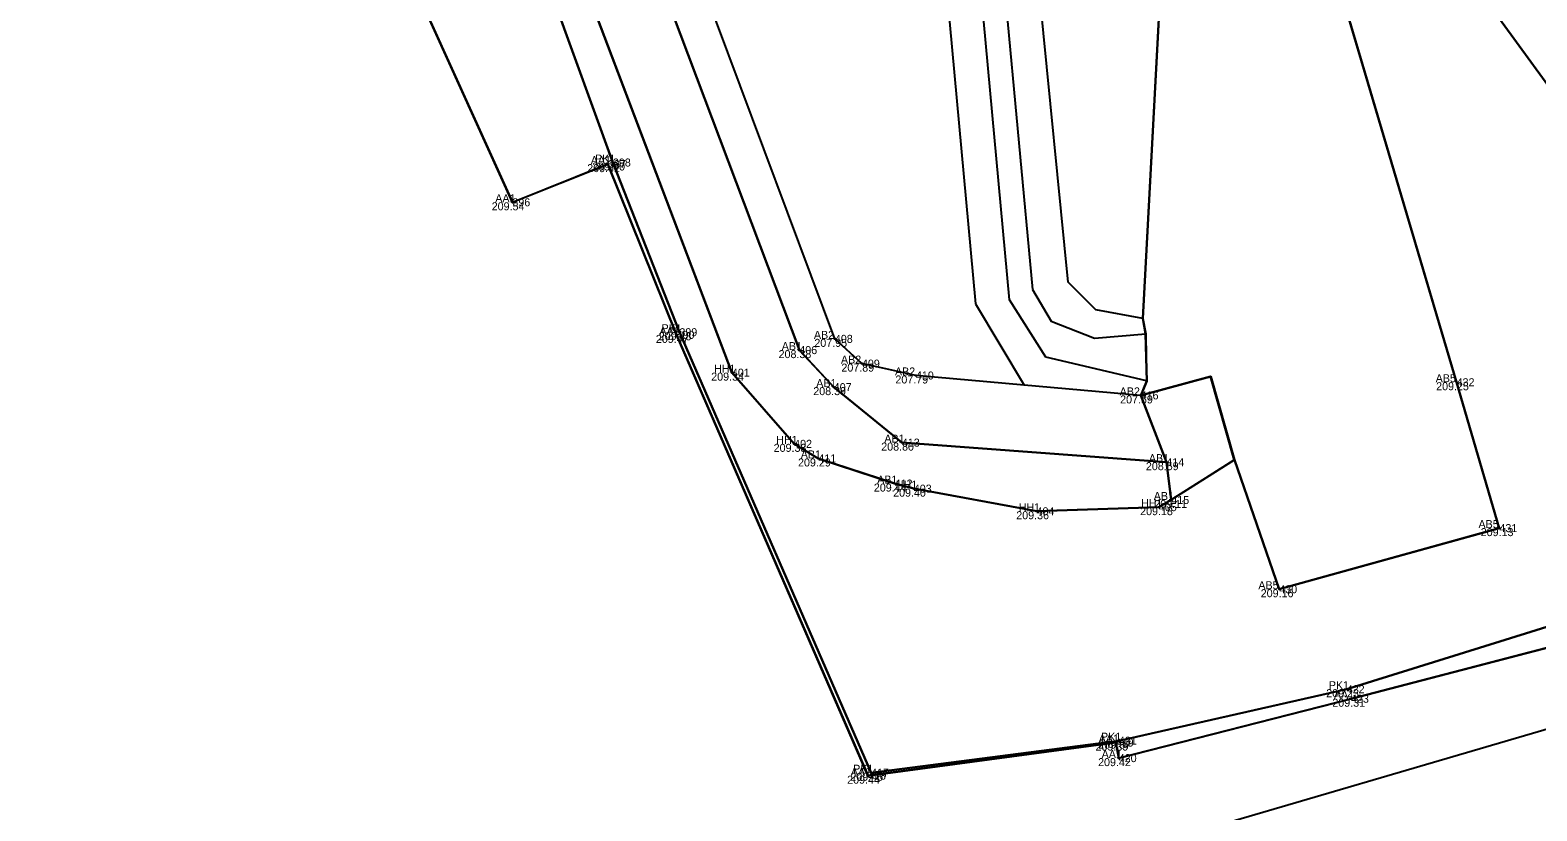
# Model space of a CAD drawing. Extents: x -263091 to -262565, y -1238731 to -1237092.
# Drawn here: x -262849.37 to -262811.71, y -1238702.72 to -1238683.21 of the extents above; entities that cross this region are included whole.
import ezdxf

# ---------------------------------------------------------------- set-up
doc = ezdxf.new("R2010")
doc.units = 0
for name, color, linetype in [('01_Hrana_betónu', 7, 'Continuous'), ('02_Oplotenie', 7, 'Continuous'), ('03_Asfalt', 7, 'Continuous'), ('05_Hrana_terénu', 7, 'Continuous'), ('07_Iné', 7, 'Continuous'), ('08_Mimo_zelene', 7, 'Continuous'), ('10', 7, 'Continuous'), ('Groma (21)', 7, 'Continuous'), ('Groma (22)', 7, 'Continuous'), ('Groma (23)', 7, 'Continuous'), ('Groma (24)', 7, 'Continuous'), ('U001_Betónové_panely_oblast', 7, 'Continuous'), ('U001_Betóny_prídavné', 7, 'Continuous'), ('U001_Ostatné_plochy', 7, 'Continuous'), ('U001_Zeleň_mimo', 7, 'Continuous'), ('U001_Zeleň_vnútro', 7, 'Continuous'), ('U001_Zeleň_zatrávňovač', 7, 'Continuous')]:
    doc.layers.add(name, color=color, linetype=linetype)

msp = doc.modelspace()

# ---------------------------------------------------------------- linework, layer by layer
at = {"layer": '01_Hrana_betónu'}
for points in [[(-262945.09, -1238415.05), (-262943.108, -1238420.999), (-262942.065, -1238424.139), (-262934.754, -1238438.855), (-262923.683, -1238461.06), (-262913.753, -1238481.232), (-262903.896, -1238501.06), (-262894.759, -1238519.856), (-262890.317, -1238530.551), (-262883.158, -1238545.169), (-262873.572, -1238564.111), (-262869.728, -1238571.951), (-262860.562, -1238590.864), (-262854.835, -1238604.812), (-262840.38, -1238642.586), (-262833.174, -1238661.935), (-262826.575, -1238681.018), (-262825.738, -1238690.053), (-262824.527, -1238692.082)], [(-262821.464, -1238691.979), (-262823.978, -1238691.385), (-262824.893, -1238689.953), (-262825.729, -1238680.825), (-262832.468, -1238661.625), (-262839.672, -1238642.452), (-262854.271, -1238604.655), (-262859.863, -1238590.55), (-262868.949, -1238571.69), (-262872.864, -1238563.867), (-262882.403, -1238544.934), (-262889.591, -1238530.296), (-262894.035, -1238519.557), (-262903.102, -1238500.748), (-262912.912, -1238480.97), (-262922.987, -1238460.594), (-262933.962, -1238438.502), (-262941.314, -1238423.977), (-262942.296, -1238420.781), (-262943.962, -1238415.15)], [(-262941.142, -1238415.313), (-262941.461, -1238420.191), (-262940.383, -1238424.238), (-262933.343, -1238438.564), (-262922.27, -1238460.876), (-262912.449, -1238480.877), (-262902.557, -1238500.683), (-262893.416, -1238519.552), (-262889.058, -1238529.686), (-262881.962, -1238544.577), (-262872.106, -1238564.019), (-262868.478, -1238571.232), (-262859.211, -1238590.61), (-262852.998, -1238605.343), (-262846.933, -1238621.173), (-262838.559, -1238643.348), (-262831.894, -1238661.158), (-262825.164, -1238680.62), (-262824.312, -1238689.696), (-262823.847, -1238690.483), (-262822.763, -1238690.91), (-262821.486, -1238690.803)], [(-262821.555, -1238690.42), (-262822.731, -1238690.203), (-262823.426, -1238689.509), (-262824.318, -1238680.43), (-262831.163, -1238660.976), (-262837.946, -1238643.111), (-262846.365, -1238620.94), (-262852.333, -1238605.156), (-262858.618, -1238590.245), (-262867.784, -1238570.905), (-262871.416, -1238563.68), (-262881.223, -1238544.283), (-262888.392, -1238529.442), (-262892.626, -1238519.239), (-262901.725, -1238500.385), (-262911.6, -1238480.51), (-262921.479, -1238460.51), (-262932.607, -1238438.043), (-262939.752, -1238424.147), (-262940.771, -1238420.267), (-262940.559, -1238417.612), (-262940.205, -1238415.315)], [(-262821.612, -1238692.34), (-262824.527, -1238692.082), (-262827.229, -1238691.842), (-262828.578, -1238691.545), (-262829.254, -1238690.927), (-262834.577, -1238676.68), (-262835.677, -1238673.797), (-262838.498, -1238665.964), (-262846.729, -1238644.188), (-262854.634, -1238622.918), (-262863.262, -1238600.529), (-262868.088, -1238589.608)], [(-262868.934, -1238589.993), (-262864.101, -1238600.869), (-262855.602, -1238623.066), (-262847.622, -1238644.482), (-262839.332, -1238666.304), (-262836.604, -1238674.133), (-262835.486, -1238677.015), (-262830.144, -1238691.208), (-262829.282, -1238692.133), (-262827.58, -1238693.519), (-262820.969, -1238694.008)], [(-262820.949, -1238674.974), (-262820.828, -1238676.721), (-262819.978, -1238676.713), (-262819.376, -1238678.614), (-262820.948, -1238679.013), (-262821.555, -1238690.42)]]:
    msp.add_lwpolyline(points, dxfattribs=at)
at = {"layer": '02_Oplotenie'}
msp.add_lwpolyline([(-262896.033, -1238537.323), (-262884.611, -1238562.768), (-262875.332, -1238581.932), (-262871.26, -1238591.133), (-262867.507, -1238600.089), (-262859.113, -1238621.74), (-262850.323, -1238645.054), (-262841.974, -1238667.148), (-262839.469, -1238673.878), (-262839.26, -1238674.43), (-262837.725, -1238678.482), (-262834.801, -1238686.521), (-262833.14, -1238690.761), (-262828.35, -1238701.769), (-262822.156, -1238700.967), (-262816.462, -1238699.68), (-262807.77, -1238696.972), (-262807.339, -1238690.207)], dxfattribs=at)
at = {"layer": '03_Asfalt'}
msp.add_lwpolyline([(-262881.2, -1238585.494), (-262874.644, -1238603.324), (-262866.886, -1238624.256), (-262857.388, -1238650.091), (-262854.721, -1238649.057), (-262851.25, -1238656.85), (-262845.959, -1238668.452), (-262837.314, -1238687.515), (-262834.926, -1238686.561), (-262833.211, -1238690.828), (-262828.426, -1238701.842), (-262822.233, -1238701.015), (-262822.159, -1238701.403), (-262816.354, -1238699.919), (-262807.207, -1238697.538)], dxfattribs=at)
at = {"layer": '05_Hrana_terénu'}
msp.add_lwpolyline([(-262820.846, -1238694.953), (-262821.157, -1238695.132), (-262824.214, -1238695.234), (-262827.282, -1238694.67), (-262827.759, -1238694.543), (-262829.668, -1238693.915), (-262830.272, -1238693.55), (-262831.828, -1238691.771), (-262836.912, -1238678.373), (-262837.725, -1238678.482), (-262838.648, -1238678.516), (-262839.921, -1238675.334), (-262839.26, -1238674.43), (-262838.626, -1238673.561), (-262840.949, -1238666.783), (-262849.249, -1238645.167), (-262857.406, -1238624.309), (-262870.41, -1238590.811)], dxfattribs=at)
at = {"layer": '07_Iné'}
msp.add_lwpolyline([(-262821.612, -1238692.34), (-262820.969, -1238694.008), (-262820.846, -1238694.953), (-262819.273, -1238693.95), (-262819.863, -1238691.866), (-262821.612, -1238692.34)], dxfattribs=at)
at = {"layer": '08_Mimo_zelene'}
msp.add_lwpolyline([(-262817.803, -1238678.214), (-262819.181, -1238678.564), (-262819.376, -1238678.614), (-262820.948, -1238679.013), (-262821.555, -1238690.42), (-262821.486, -1238690.803), (-262821.464, -1238691.979), (-262821.612, -1238692.34), (-262819.863, -1238691.866), (-262819.273, -1238693.95), (-262818.147, -1238697.183), (-262812.645, -1238695.656), (-262813.715, -1238692.011)], close=True, dxfattribs=at)
at = {"layer": '10'}
msp.add_line((-262857.845, -1238714.263), (-262769.355, -1238688.329), dxfattribs=at)
at = {"layer": 'Groma (21)'}
for centre in [(-262834.926, -1238686.561), (-262834.801, -1238686.521), (-262837.314, -1238687.515), (-262833.211, -1238690.828), (-262833.14, -1238690.761), (-262829.254, -1238690.927), (-262830.144, -1238691.208), (-262831.828, -1238691.771), (-262828.578, -1238691.545), (-262829.282, -1238692.133), (-262827.229, -1238691.842), (-262813.715, -1238692.011), (-262821.612, -1238692.34), (-262830.272, -1238693.55), (-262827.58, -1238693.519), (-262829.668, -1238693.915), (-262820.969, -1238694.008), (-262827.759, -1238694.543), (-262827.282, -1238694.67), (-262821.157, -1238695.132), (-262820.846, -1238694.953), (-262824.214, -1238695.234), (-262812.645, -1238695.656), (-262818.147, -1238697.183), (-262816.462, -1238699.68), (-262816.354, -1238699.919), (-262822.233, -1238701.015), (-262822.156, -1238700.967), (-262822.159, -1238701.403), (-262828.426, -1238701.842), (-262828.35, -1238701.769)]:
    msp.add_circle(centre, 0.01, dxfattribs=at)
at = {"layer": 'U001_Betónové_panely_oblast'}
for points in [[(-262820.97, -1238694.01), (-262827.58, -1238693.52), (-262829.28, -1238692.13), (-262830.14, -1238691.21), (-262835.49, -1238677.02), (-262836.6, -1238674.13), (-262839.33, -1238666.3), (-262847.62, -1238644.48), (-262855.6, -1238623.07), (-262864.1, -1238600.87), (-262868.93, -1238589.99)], [(-262848.87, -1238596.84), (-262845.92, -1238603.87), (-262845.19, -1238603.53), (-262840.99, -1238614.59), (-262831.97, -1238638.45), (-262824.36, -1238658.57), (-262825.01, -1238658.87), (-262822.4, -1238666.1), (-262821.67, -1238665.91), (-262820.09, -1238675), (-262820.95, -1238674.97), (-262820.83, -1238676.72), (-262819.98, -1238676.71), (-262819.38, -1238678.61), (-262820.95, -1238679.01), (-262821.56, -1238690.42), (-262821.49, -1238690.8), (-262821.46, -1238691.98), (-262821.61, -1238692.34), (-262820.97, -1238694.01)], [(-262825.01, -1238658.87), (-262822.4, -1238666.1), (-262821.67, -1238665.91), (-262820.09, -1238675), (-262820.95, -1238674.97), (-262820.83, -1238676.72), (-262819.98, -1238676.71), (-262819.38, -1238678.61), (-262820.95, -1238679.01), (-262821.56, -1238690.42), (-262821.49, -1238690.8), (-262821.46, -1238691.98), (-262821.61, -1238692.34), (-262820.97, -1238694.01), (-262827.58, -1238693.52), (-262829.28, -1238692.13), (-262830.14, -1238691.21), (-262835.49, -1238677.02), (-262836.6, -1238674.13), (-262839.33, -1238666.3), (-262847.62, -1238644.48)]]:
    msp.add_lwpolyline(points, dxfattribs=at)
at = {"layer": 'U001_Betóny_prídavné'}
msp.add_lwpolyline([(-262819.27, -1238693.95), (-262820.85, -1238694.95), (-262820.97, -1238694.01), (-262821.61, -1238692.34), (-262819.86, -1238691.87)], close=True, dxfattribs=at)
msp.add_lwpolyline([(-262820.85, -1238694.95), (-262820.97, -1238694.01), (-262821.61, -1238692.34), (-262819.86, -1238691.87), (-262819.27, -1238693.95), (-262820.85, -1238694.95)], dxfattribs=at)
at = {"layer": 'U001_Ostatné_plochy'}
msp.add_lwpolyline([(-262818.15, -1238697.18), (-262819.27, -1238693.95), (-262819.86, -1238691.87), (-262821.61, -1238692.34), (-262821.46, -1238691.98), (-262821.49, -1238690.8), (-262821.56, -1238690.42), (-262820.95, -1238679.01), (-262819.38, -1238678.61), (-262819.18, -1238678.56), (-262817.8, -1238678.21), (-262813.72, -1238692.01), (-262812.65, -1238695.66)], close=True, dxfattribs=at)
msp.add_lwpolyline([(-262818.15, -1238697.18), (-262819.27, -1238693.95), (-262819.86, -1238691.87), (-262821.61, -1238692.34), (-262821.46, -1238691.98), (-262821.49, -1238690.8), (-262821.56, -1238690.42), (-262820.95, -1238679.01), (-262819.38, -1238678.61), (-262819.18, -1238678.56), (-262817.8, -1238678.21), (-262813.72, -1238692.01), (-262812.65, -1238695.66), (-262818.15, -1238697.18)], dxfattribs=at)
at = {"layer": 'U001_Zeleň_mimo'}
for points in [[(-262807.21, -1238697.54), (-262816.35, -1238699.92), (-262822.16, -1238701.4), (-262822.23, -1238701.02), (-262828.43, -1238701.84), (-262833.21, -1238690.83), (-262834.93, -1238686.56), (-262837.31, -1238687.52), (-262845.96, -1238668.45), (-262851.25, -1238656.85), (-262854.72, -1238649.06), (-262857.39, -1238650.09), (-262866.89, -1238624.26), (-262874.64, -1238603.32), (-262881.2, -1238585.49)], [(-262871.26, -1238591.13), (-262867.51, -1238600.09), (-262859.11, -1238621.74), (-262850.32, -1238645.05), (-262841.97, -1238667.15), (-262839.47, -1238673.88), (-262839.26, -1238674.43), (-262837.72, -1238678.48), (-262834.8, -1238686.52), (-262833.14, -1238690.76), (-262828.35, -1238701.77), (-262822.16, -1238700.97), (-262816.46, -1238699.68), (-262807.77, -1238696.97)], [(-262807.34, -1238690.21), (-262818.53, -1238674.84), (-262818.69, -1238673.95), (-262819.78, -1238666.25), (-262819.69, -1238665.25), (-262822.28, -1238657.84), (-262830.39, -1238637.77), (-262839.6, -1238613.33), (-262842.24, -1238606.86), (-262843.24, -1238602.62), (-262846.18, -1238595.66)]]:
    msp.add_lwpolyline(points, dxfattribs=at)
at = {"layer": 'U001_Zeleň_vnútro'}
for points in [[(-262870.41, -1238590.81), (-262857.41, -1238624.31), (-262849.25, -1238645.17), (-262840.95, -1238666.78), (-262838.63, -1238673.56), (-262837.73, -1238674.66), (-262836.74, -1238677.38), (-262836.91, -1238678.37), (-262831.83, -1238691.77), (-262830.27, -1238693.55), (-262829.67, -1238693.92), (-262827.76, -1238694.54), (-262827.28, -1238694.67), (-262824.21, -1238695.23), (-262821.16, -1238695.13), (-262820.85, -1238694.95), (-262819.27, -1238693.95), (-262818.15, -1238697.18), (-262812.65, -1238695.66), (-262813.72, -1238692.01), (-262817.8, -1238678.21), (-262818.53, -1238674.84), (-262807.34, -1238690.21)], [(-262870.41, -1238590.81), (-262857.41, -1238624.31), (-262849.25, -1238645.17), (-262840.95, -1238666.78), (-262838.63, -1238673.56), (-262837.73, -1238674.66), (-262836.74, -1238677.38), (-262836.91, -1238678.37), (-262831.83, -1238691.77), (-262830.27, -1238693.55), (-262829.67, -1238693.92), (-262827.76, -1238694.54), (-262827.28, -1238694.67), (-262824.21, -1238695.23), (-262821.16, -1238695.13), (-262820.85, -1238694.95), (-262819.27, -1238693.95), (-262818.15, -1238697.18), (-262812.65, -1238695.66), (-262813.72, -1238692.01), (-262817.8, -1238678.21), (-262818.53, -1238674.84), (-262807.34, -1238690.21)], [(-262807.77, -1238696.97), (-262816.46, -1238699.68), (-262822.16, -1238700.97), (-262828.35, -1238701.77), (-262833.14, -1238690.76), (-262834.8, -1238686.52), (-262837.72, -1238678.48), (-262839.26, -1238674.43), (-262839.47, -1238673.88), (-262841.97, -1238667.15), (-262850.32, -1238645.05), (-262859.11, -1238621.74), (-262867.51, -1238600.09), (-262871.26, -1238591.13)], [(-262828.35, -1238701.77), (-262833.14, -1238690.76), (-262834.8, -1238686.52), (-262837.72, -1238678.48), (-262839.26, -1238674.43), (-262839.47, -1238673.88), (-262841.97, -1238667.15), (-262850.32, -1238645.05), (-262859.11, -1238621.74), (-262867.51, -1238600.09), (-262871.26, -1238591.13)], [(-262807.77, -1238696.97), (-262816.46, -1238699.68), (-262822.16, -1238700.97), (-262828.35, -1238701.77)]]:
    msp.add_lwpolyline(points, dxfattribs=at)
at = {"layer": 'U001_Zeleň_zatrávňovač'}
msp.add_lwpolyline([(-262836.91, -1238678.37), (-262836.74, -1238677.38), (-262835.49, -1238677.02), (-262830.14, -1238691.21), (-262829.28, -1238692.13), (-262827.58, -1238693.52), (-262820.97, -1238694.01), (-262820.85, -1238694.95), (-262821.16, -1238695.13), (-262824.21, -1238695.23), (-262827.28, -1238694.67), (-262827.76, -1238694.54), (-262829.67, -1238693.92), (-262830.27, -1238693.55), (-262831.83, -1238691.77)], close=True, dxfattribs=at)
msp.add_lwpolyline([(-262824.21, -1238695.23), (-262827.28, -1238694.67), (-262827.76, -1238694.54), (-262829.67, -1238693.92), (-262830.27, -1238693.55), (-262831.83, -1238691.77), (-262836.91, -1238678.37), (-262836.74, -1238677.38), (-262835.49, -1238677.02), (-262830.14, -1238691.21), (-262829.28, -1238692.13), (-262827.58, -1238693.52), (-262820.97, -1238694.01), (-262820.85, -1238694.95), (-262821.16, -1238695.13), (-262824.21, -1238695.23)], dxfattribs=at)

# ---------------------------------------------------------------- texts
at = {"layer": 'Groma (22)'}
for s, p in [('397', (-262834.926, -1238686.661)), ('398', (-262834.801, -1238686.621)), ('396', (-262837.314, -1238687.615)), ('400', (-262833.211, -1238690.928)), ('399', (-262833.14, -1238690.861)), ('408', (-262829.254, -1238691.027)), ('406', (-262830.144, -1238691.308)), ('401', (-262831.828, -1238691.871)), ('409', (-262828.578, -1238691.645)), ('410', (-262827.229, -1238691.942)), ('407', (-262829.282, -1238692.233)), ('432', (-262813.715, -1238692.111)), ('416', (-262821.612, -1238692.44)), ('402', (-262830.272, -1238693.65)), ('413', (-262827.58, -1238693.619)), ('411', (-262829.668, -1238694.015)), ('414', (-262820.969, -1238694.108)), ('412', (-262827.759, -1238694.643)), ('403', (-262827.282, -1238694.77)), ('404', (-262824.214, -1238695.334)), ('405', (-262821.157, -1238695.232)), ('415', (-262820.846, -1238695.053)), ('431', (-262812.645, -1238695.756)), ('430', (-262818.147, -1238697.283)), ('422', (-262816.462, -1238699.78)), ('423', (-262816.354, -1238700.019)), ('419', (-262822.233, -1238701.115)), ('421', (-262822.156, -1238701.067)), ('420', (-262822.159, -1238701.503)), ('418', (-262828.426, -1238701.942)), ('417', (-262828.35, -1238701.869))]:
    msp.add_text(s, height=0.2, dxfattribs=at).set_placement(p)
at = {"layer": 'Groma (23)'}
for s, p in [('209.42', (-262835.443, -1238686.761)), ('209.40', (-262835.317, -1238686.721)), ('209.54', (-262837.831, -1238687.715)), ('209.47', (-262833.728, -1238691.028)), ('209.48', (-262833.657, -1238690.961)), ('207.95', (-262829.767, -1238691.127)), ('208.38', (-262830.661, -1238691.408)), ('209.34', (-262832.345, -1238691.971)), ('207.89', (-262829.091, -1238691.745)), ('208.39', (-262829.794, -1238692.333)), ('207.79', (-262827.742, -1238692.042)), ('209.25', (-262814.227, -1238692.211)), ('207.59', (-262822.125, -1238692.54)), ('209.33', (-262830.784, -1238693.75)), ('208.80', (-262828.096, -1238693.719)), ('209.29', (-262830.175, -1238694.115)), ('208.59', (-262821.481, -1238694.208)), ('209.44', (-262828.28, -1238694.743)), ('209.40', (-262827.798, -1238694.87)), ('209.18', (-262821.625, -1238695.332)), ('209.11', (-262821.271, -1238695.153)), ('209.36', (-262824.721, -1238695.434)), ('209.13', (-262813.113, -1238695.856)), ('209.16', (-262818.611, -1238697.383)), ('209.23', (-262816.974, -1238699.88)), ('209.31', (-262816.822, -1238700.119)), ('209.39', (-262822.74, -1238701.215)), ('209.37', (-262822.669, -1238701.167)), ('209.42', (-262822.676, -1238701.603)), ('209.44', (-262828.947, -1238702.042)), ('209.45', (-262828.867, -1238701.969))]:
    msp.add_text(s, height=0.2, dxfattribs=at).set_placement(p)
at = {"layer": 'Groma (24)'}
for s, p in [('AA1', (-262835.354, -1238686.561)), ('PK1', (-262835.248, -1238686.521)), ('AA1', (-262837.742, -1238687.515)), ('AA1', (-262833.639, -1238690.828)), ('PK1', (-262833.587, -1238690.761)), ('AB1', (-262830.582, -1238691.208)), ('AB2', (-262829.778, -1238690.927)), ('AB2', (-262829.102, -1238691.545)), ('HH1', (-262832.275, -1238691.771)), ('AB2', (-262827.753, -1238691.842)), ('AB1', (-262829.72, -1238692.133)), ('AB2', (-262822.136, -1238692.34)), ('AB5', (-262814.239, -1238692.011)), ('HH1', (-262830.719, -1238693.55)), ('AB1', (-262828.018, -1238693.519)), ('AB1', (-262830.106, -1238693.915)), ('AB1', (-262821.407, -1238694.008)), ('AB1', (-262828.197, -1238694.543)), ('HH1', (-262827.729, -1238694.67)), ('AB1', (-262821.284, -1238694.953)), ('HH1', (-262824.661, -1238695.234)), ('HH1', (-262821.604, -1238695.132)), ('AB5', (-262813.169, -1238695.656)), ('AB5', (-262818.671, -1238697.183)), ('PK1', (-262816.909, -1238699.68)), ('AA1', (-262816.782, -1238699.919)), ('AA1', (-262822.661, -1238701.015)), ('PK1', (-262822.603, -1238700.967)), ('AA1', (-262822.587, -1238701.403)), ('AA1', (-262828.854, -1238701.842)), ('PK1', (-262828.797, -1238701.769))]:
    msp.add_text(s, height=0.2, dxfattribs=at).set_placement(p)

doc.saveas('drawing.dxf')
